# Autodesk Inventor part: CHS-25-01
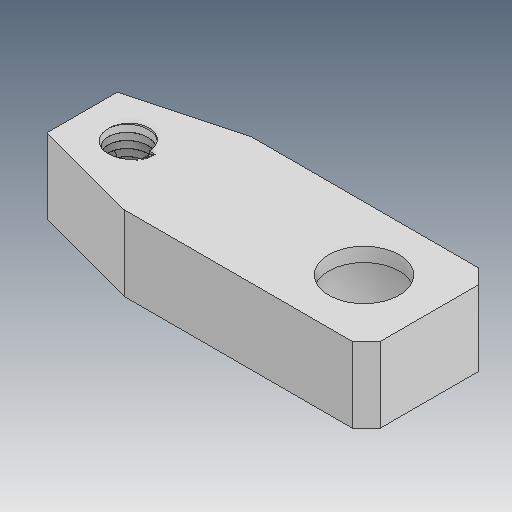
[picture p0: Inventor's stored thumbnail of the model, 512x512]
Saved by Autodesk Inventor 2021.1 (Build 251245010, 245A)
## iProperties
Created: 2019-05
Part Number: CHS-25-01
Material: Ogólny
Document SubType Name: Modeling
Designer: user
Density: 1 g/cm^3
Appearance: Domyślna
Author: user
Revision Number: ÈÎºÎ
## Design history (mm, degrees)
feature "ÊäÈë1"
node "Bryła1"
